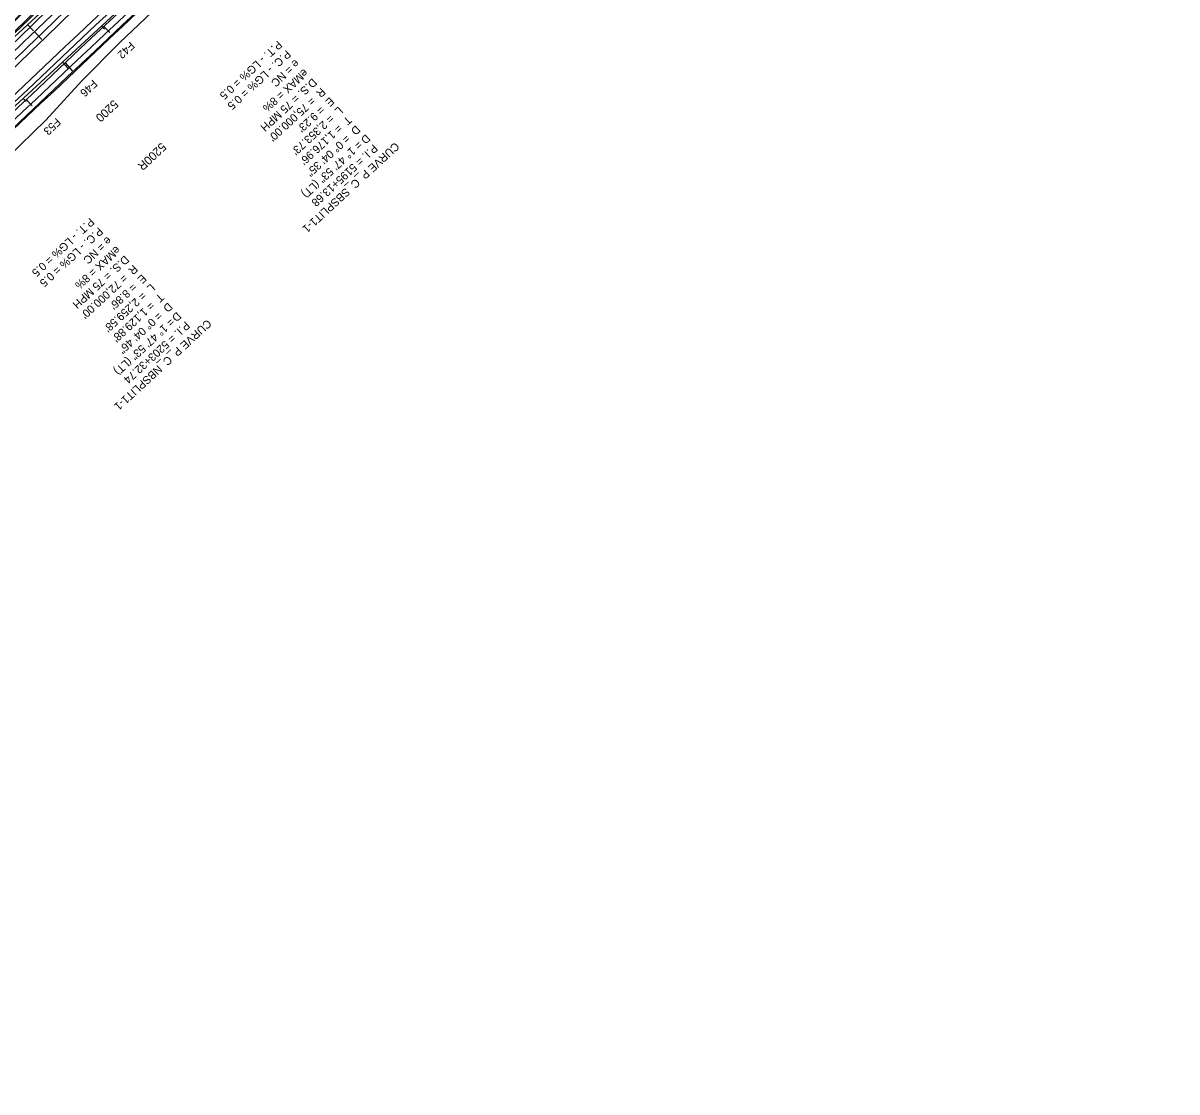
# Model space of a CAD drawing. Extents: x 2160877 to 2175861, y 601747 to 617724.
# Drawn here: x 2170110 to 2172272, y 609847 to 611849 of the extents above; entities that cross this region are included whole.
import ezdxf

# ---------------------------------------------------------------- set-up
doc = ezdxf.new("R2010")
doc.units = 0
for name, color, linetype in [('RD_HC_Cl', 7, 'Continuous'), ('RD_HC_CL_Rel', 7, 'Continuous'), ('RD_HC_Data_Rel', 7, 'Continuous'), ('RD_HC_Data_Tic', 7, 'Continuous'), ('RD_HC_Data_Tic_Rel', 7, 'Continuous'), ('RD_HC_TX_Rel_Sta50', 7, 'Continuous'), ('RD_HC_TX_StaOther', 7, 'Continuous'), ('RD_PD_CstnLmt', 7, 'Continuous'), ('RD_PD_CstnLmt_TX', 7, 'Continuous'), ('RD_PD_Final_LnLine', 7, 'Continuous'), ('RD_PD_Final_TrvlWay', 7, 'Continuous'), ('RD_PD_GR', 7, 'Continuous'), ('RD_PD_MedBWall', 7, 'Continuous')]:
    doc.layers.add(name, color=color, linetype=linetype)

msp = doc.modelspace()

# ---------------------------------------------------------------- linework, layer by layer
at = {"layer": 'RD_HC_Cl'}
for p, q in [((2172207.3, 613775.1), (2163672.2, 605893.8)), ((2172272.5, 613704.6), (2163737.4, 605823.3))]:
    msp.add_line(p, q, dxfattribs=at)
at = {"layer": 'RD_HC_CL_Rel'}
for centre, radius in [((2222221.5, 557873.6), 75000), ((2219616.9, 559421.3), 72000)]:
    msp.add_arc(centre, radius, 132.719474, 134.517591, dxfattribs=at)
at = {"layer": 'RD_HC_Data_Tic'}
for p, q in [((2170118.8, 611846.6), (2170129.6, 611834.8)), ((2170257.4, 611843.9), (2170262.8, 611838)), ((2170183.9, 611776), (2170194.7, 611764.3)), ((2170110.4, 611708.2), (2170115.9, 611702.3))]:
    msp.add_line(p, q, dxfattribs=at)
at = {"layer": 'RD_HC_Data_Tic_Rel'}
for p, q in [((2170131.4, 611833.1), (2170145.3, 611818.7)), ((2170261.6, 611843.2), (2170272.5, 611831.5)), ((2170188.8, 611774.6), (2170202.5, 611760)), ((2170116.1, 611705.9), (2170127.1, 611694.2))]:
    msp.add_line(p, q, dxfattribs=at)
at = {"layer": 'RD_PD_CstnLmt'}
for p, q in [((2170363.2, 611881), (2170290.7, 611812.3)), ((2170290.7, 611812.3), (2170220.6, 611740.9)), ((2170220.6, 611740.9), (2170152.7, 611667.2)), ((2170152.7, 611667.2), (2170081.3, 611597.4))]:
    msp.add_line(p, q, dxfattribs=at)
at = {"layer": 'RD_PD_Final_LnLine'}
for centre, radius in [((2222221.5, 557873.6), 75012), ((2222221.5, 557873.6), 74988), ((2219616.9, 559421.3), 72012), ((2219616.9, 559421.3), 71988)]:
    msp.add_arc(centre, radius, 132.719474, 134.517591, dxfattribs=at)
at = {"layer": 'RD_PD_Final_TrvlWay'}
for centre, radius in [((2222220.1, 557875.1), 75024.3), ((2222220.1, 557875.1), 75022), ((2222221.5, 557873.6), 74978), ((2219616.9, 559421.3), 72022), ((2219616.9, 559421.3), 71978)]:
    msp.add_arc(centre, radius, 132.719474, 134.517591, dxfattribs=at)
at = {"layer": 'RD_PD_GR'}
msp.add_arc((2219616.9, 559421.3), 71976, 132.719474, 134.517591, dxfattribs=at)
at = {"layer": 'RD_PD_MedBWall'}
for radius, end in [(75039.3, 134.421287), (75038.3, 134.421298)]:
    msp.add_arc((2222220.1, 557875.1), radius, 132.719474, end, dxfattribs=at)

# ---------------------------------------------------------------- texts
at = {"layer": 'RD_HC_Data_Rel'}
for s, p in [('P.T. - LG% = 0.5', (2170587.3, 611817.4)), ('P.C. - LG% = 0.5', (2170603.6, 611799.8)), ('e = NC', (2170619.8, 611782.1)), ('D.S. = 75 MPH', (2170652.4, 611746.9)), ('eMAX = 8%', (2170636.1, 611764.5)), ("R  = 75,000.00'", (2170668.7, 611729.2)), ("E  = 9.23'", (2170685, 611711.6)), ("L  = 2,353.73'", (2170701.2, 611694)), ("T  = 1,176.96'", (2170717.5, 611676.3)), ('D  = 0%%d 04\' 35"', (2170733.8, 611658.7)), ('D ', (2170752.4, 611642.1)), ('   = 1%%d 47\' 53" (LT)', (2170750.1, 611641.1)), ('CURVE P_C_SBSPLIT1-1', (2170806.9, 611627.1)), ('P.I. = 5195+13.68', (2170766.4, 611623.4)), ('P.T. - LG% = 0.5', (2170235.4, 611485.5)), ('P.C. - LG% = 0.5', (2170251.7, 611467.9)), ('e = NC', (2170268, 611450.2)), ('eMAX = 8%', (2170284.2, 611432.6)), ('D.S. = 75 MPH', (2170300.5, 611415)), ("R  = 72,000.00'", (2170316.8, 611397.3)), ("E  = 8.86'", (2170333.1, 611379.7)), ("L  = 2,259.58'", (2170349.4, 611362.1)), ("T  = 1,129.88'", (2170365.7, 611344.4)), ('D  = 0%%d 04\' 46"', (2170381.9, 611326.8)), ('   = 1%%d 47\' 53" (LT)', (2170398.2, 611309.2)), ('CURVE P_C_NBSPLIT1-1', (2170455, 611295.2)), ('P.I. = 5203+32.74', (2170414.5, 611291.5)), ('D ', (2170398.2, 611309.2))]:
    msp.add_text(s, height=15, rotation=222.7195, dxfattribs=at).set_placement(p)
at = {"layer": 'RD_HC_TX_Rel_Sta50'}
msp.add_text('5200R', height=16, rotation=223.3538, dxfattribs=at).set_placement((2170369.3, 611626.5))
at = {"layer": 'RD_HC_TX_StaOther'}
msp.add_text('5200', height=16, rotation=222.7195, dxfattribs=at).set_placement((2170279.7, 611706.6))
at = {"layer": 'RD_PD_CstnLmt_TX'}
for s, rotation, p in [('F42', 223.2742, (2170310.7, 611815.7)), ('F46', 223.3538, (2170240.8, 611744.4)), ('F53', 223.4334, (2170172.3, 611672.6))]:
    msp.add_text(s, height=15, rotation=rotation, dxfattribs=at).set_placement(p)

doc.saveas('drawing.dxf')
